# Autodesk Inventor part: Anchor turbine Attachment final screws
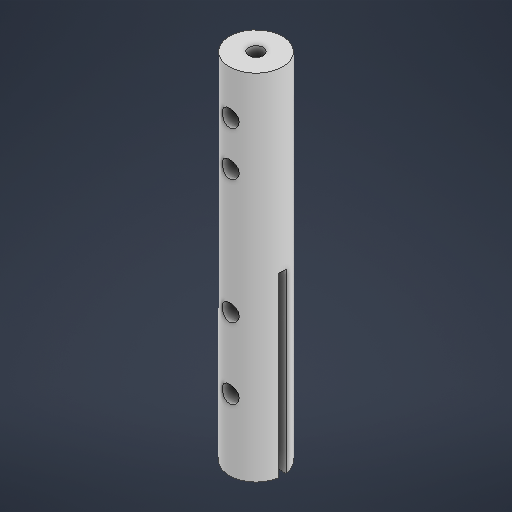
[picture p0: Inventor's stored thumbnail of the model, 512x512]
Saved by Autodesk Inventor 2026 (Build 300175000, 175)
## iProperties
Created: 2025-10
Part Number: Anchor turbine Attachment final screws
Material: Generic
Document SubType Name: Modeling
Designer: sab273
Density: 1 g/cm^3
Appearance: Default
Author: sab273
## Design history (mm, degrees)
sketch "Sketch1"
  geometry: C1 r 7.5 at (0, 0); 1 further point
  constraints: 1 centre point, 1 coincident
  dimensions: "d0" = 15 diameter of C1
extrude "Extrusion1" new body sketch "Sketch1" distance "d1" = 100; taper "d2" = 0 deg
sketch "Sketch4"
  geometry: 1 further point
sketch "Sketch5"
  geometry: L1 (-7.426, 1.05)-(7.426, 1.05); L2 (-7.426, -1.05)-(7.426, -1.05); A1 r 7.5 centre (0, 0) between (-7.426, 1.05) and (-7.426, -1.05) reference; 1 further point
  constraints: 4 end point, 4 point on circle
extrude "Extrusion4" cut sketch "Sketch5" distance "d12" = 50; taper "d13" = 0 deg
sketch "Sketch10"
  geometry: C1 r 2.4 at (7.426, 20); C2 r 2.4 at (7.426, 40); 1 further point
  constraints: 2 centre point
extrude "Extrusion6" cut sketch "Sketch10" distance "d22" = 7.5; taper "d23" = 0 deg
sketch "Sketch11"
  geometry: C1 r 2.4 at (7.426, 20); C2 r 2.4 at (7.426, 40); 1 further point
  constraints: 2 centre point
extrude "Extrusion7" cut sketch "Sketch11" distance "d28" = 7.5; taper "d29" = 0 deg
sketch "Sketch12"
  geometry: C1 r 2.05 at (0, 0); 1 further point
  constraints: 1 centre point, 1 coincident
  dimensions: "d30" = 4.1 diameter of C1
extrude "Extrusion8" cut sketch "Sketch12" distance "d31" = 30; taper "d32" = 0 deg
workplane "Work Plane2"
workplane "Work Plane3"
sketch "Sketch13"
  geometry: L1 (0, 0)-(26.926, 70); L2 (26.926, 70)-(0, 0); L3 (-2.05, 70)-(2.05, 70) reference; L4 (0, 70)-(0, 75); L5 (0, 75)-(0, 87.5); L6 (7.5, 100)-(-7.5, 100) reference; C1 r 2.4 at (0, 75); C2 r 2.4 at (0, 87.5)
  constraints: 8 end point, 2 centre point, 2 coincident, 1 collinear, 1 midpoint, 1 perpendicular, 1 vertical
  dimensions: "d33" = 75 distance of L1.start L1.end; "d34" = 5 distance of L4.start L4.end; "d35" = 4.8 diameter of C1; "d36" = 12.5 distance of L5.start L5.end; "d37" = 4.8 diameter of C2
extrude "Extrusion9" cut sketch "Sketch13" stored distance "d38" = 40; taper "d39" = 0 deg
body "Solid1"
